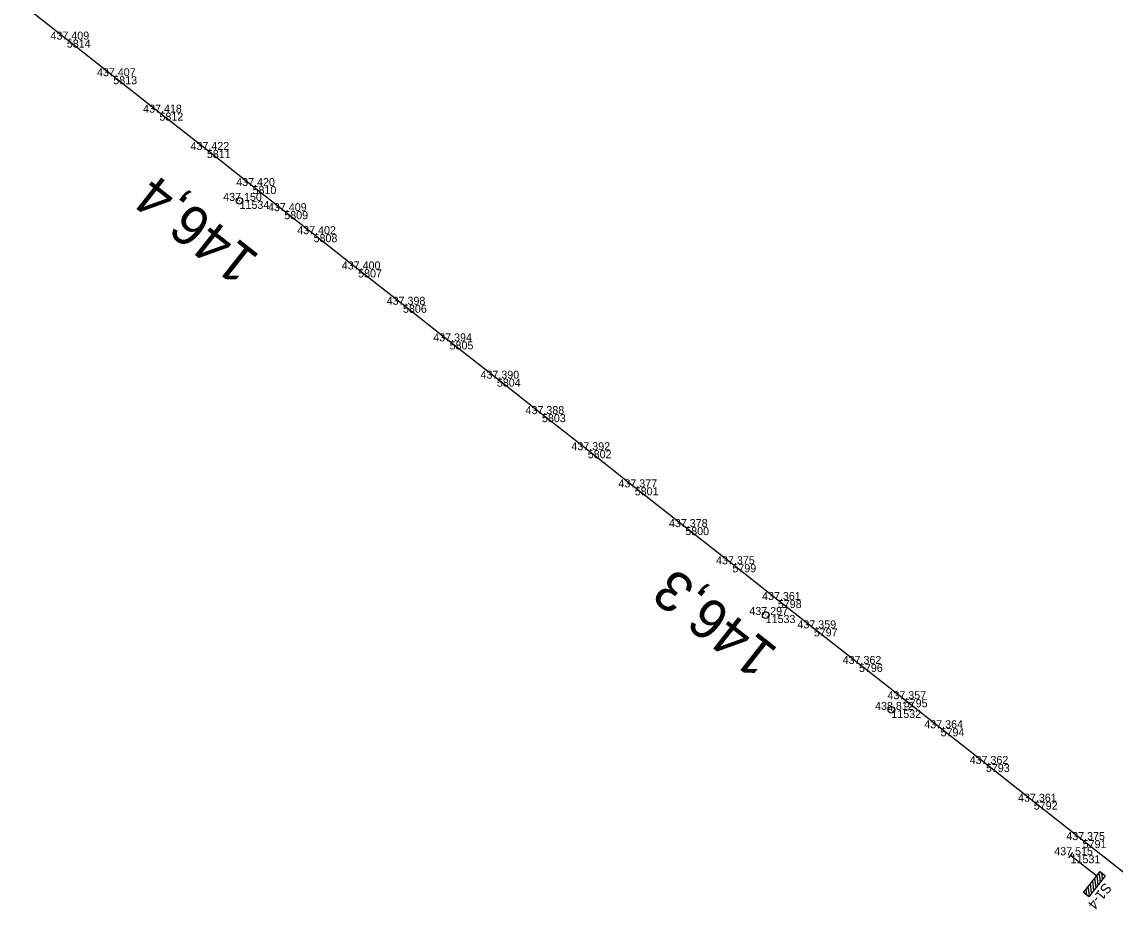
# Model space of a CAD drawing. Extents: x -654154 to -652650, y -1166925 to -1164904.
# Drawn here: x -653146.3 to -652982.4, y -1166045.8 to -1165912.8 of the extents above; entities that cross this region are included whole.
import ezdxf

# ---------------------------------------------------------------- set-up
doc = ezdxf.new("R2010")
doc.units = 0
for name, color, linetype in [('Vrstva 1', 7, 'Continuous'), ('Vrstva 50', 7, 'Continuous'), ('Vrstva 6', 7, 'Continuous'), ('Vrstva 60', 7, 'Continuous'), ('Vrstva 61', 7, 'Continuous'), ('Vrstva 7', 7, 'Continuous')]:
    doc.layers.add(name, color=color, linetype=linetype)

msp = doc.modelspace()

# ---------------------------------------------------------------- linework, layer by layer
at = {"layer": 'Vrstva 1'}
msp.add_lwpolyline([(-652979.33, -1166041.69), (-652987.25, -1166035.46), (-652994.58, -1166029.7), (-653001.76, -1166024.05), (-653008.55, -1166018.7), (-653014.07, -1166014.35), (-653020.79, -1166009.06), (-653027.56, -1166003.73), (-653032.96, -1165999.48), (-653039.77, -1165994.12), (-653046.84, -1165988.55), (-653054.41, -1165982.59), (-653061.46, -1165977.03), (-653068.33, -1165971.62), (-653075.09, -1165966.3), (-653082.18, -1165960.72), (-653089.16, -1165955.23), (-653095.89, -1165949.93), (-653102.57, -1165944.65), (-653106.96, -1165941.2), (-653111.72, -1165937.44), (-653118.57, -1165932.03), (-653125.68, -1165926.44), (-653132.6, -1165920.98), (-653139.57, -1165915.49), (-653146.31, -1165910.17)], dxfattribs=at)
at = {"layer": 'Vrstva 50'}
msp.add_line((-653015.98, -1166015.95), (-653015.88, -1166015.95), dxfattribs=at)
msp.add_circle((-653015.93, -1166015.95), 0.5, dxfattribs=at)
at = {"layer": 'Vrstva 6'}
for p, q in [((-652988.75, -1166037.33), (-652989.36, -1166038.12)), ((-652989.06, -1166037.73), (-652985.14, -1166040.81)), ((-652984.59, -1166041.72), (-652984.76, -1166040.32)), ((-652984.26, -1166041.3), (-652984.37, -1166040.4)), ((-652985.9, -1166043.39), (-652986.07, -1166041.98)), ((-652985.57, -1166042.97), (-652985.74, -1166041.57)), ((-652985.24, -1166042.55), (-652985.41, -1166041.15)), ((-652984.92, -1166042.14), (-652985.08, -1166040.73)), ((-652986.62, -1166043.72), (-652986.72, -1166042.81)), ((-652986.23, -1166043.8), (-652986.4, -1166042.4))]:
    msp.add_line(p, q, dxfattribs=at)
msp.add_lwpolyline([(-652984.65, -1166040.18), (-652983.86, -1166040.8), (-652986.34, -1166043.94), (-652987.12, -1166043.32)], close=True, dxfattribs=at)
at = {"layer": 'Vrstva 60'}
for p, q in [((-653139.57, -1165915.49), (-653139.57, -1165915.49)), ((-653132.6, -1165920.98), (-653132.6, -1165920.98)), ((-653125.68, -1165926.44), (-653125.68, -1165926.44)), ((-653118.57, -1165932.03), (-653118.57, -1165932.03)), ((-653111.72, -1165937.44), (-653111.72, -1165937.44)), ((-653113.67, -1165939.66), (-653113.67, -1165939.66)), ((-653106.96, -1165941.2), (-653106.96, -1165941.2)), ((-653102.57, -1165944.65), (-653102.57, -1165944.65)), ((-653095.89, -1165949.93), (-653095.89, -1165949.93)), ((-653089.16, -1165955.23), (-653089.16, -1165955.23)), ((-653082.18, -1165960.72), (-653082.18, -1165960.72)), ((-653075.09, -1165966.3), (-653075.09, -1165966.3)), ((-653068.33, -1165971.62), (-653068.33, -1165971.62)), ((-653061.46, -1165977.03), (-653061.46, -1165977.03)), ((-653054.41, -1165982.59), (-653054.41, -1165982.59)), ((-653046.84, -1165988.55), (-653046.84, -1165988.55)), ((-653039.77, -1165994.12), (-653039.77, -1165994.12)), ((-653032.96, -1165999.48), (-653032.96, -1165999.48)), ((-653034.78, -1166001.73), (-653034.78, -1166001.73)), ((-653027.56, -1166003.73), (-653027.56, -1166003.73)), ((-653020.79, -1166009.06), (-653020.79, -1166009.06)), ((-653014.07, -1166014.35), (-653014.07, -1166014.35)), ((-653015.93, -1166015.95), (-653015.93, -1166015.95)), ((-653008.55, -1166018.7), (-653008.55, -1166018.7)), ((-653001.76, -1166024.05), (-653001.76, -1166024.05)), ((-652994.58, -1166029.7), (-652994.58, -1166029.7)), ((-652987.25, -1166035.46), (-652987.25, -1166035.46)), ((-652989.06, -1166037.73), (-652989.06, -1166037.73))]:
    msp.add_line(p, q, dxfattribs=at)
at = {"layer": 'Vrstva 7'}
for p, q in [((-653113.63, -1165939.69), (-653113.71, -1165939.63)), ((-653034.74, -1166001.76), (-653034.82, -1166001.7))]:
    msp.add_line(p, q, dxfattribs=at)
for centre in [(-653113.67, -1165939.66), (-653034.78, -1166001.73)]:
    msp.add_circle(centre, 0.5, dxfattribs=at)

# ---------------------------------------------------------------- texts
at = {"layer": 'Vrstva 6'}
msp.add_text('S1-4', height=1.5, rotation=231.7942, dxfattribs=at).set_placement((-652983.95, -1166041.75))
at = {"layer": 'Vrstva 60'}
for s, p in [('5814', (-653139.57, -1165916.69)), ('5813', (-653132.6, -1165922.18)), ('5812', (-653125.68, -1165927.64)), ('5811', (-653118.57, -1165933.24)), ('5810', (-653111.72, -1165938.64)), ('11534', (-653113.67, -1165940.86)), ('5809', (-653106.96, -1165942.4)), ('5808', (-653102.57, -1165945.85)), ('5807', (-653095.89, -1165951.13)), ('5806', (-653089.16, -1165956.43)), ('5805', (-653082.18, -1165961.92)), ('5804', (-653075.09, -1165967.5)), ('5803', (-653068.33, -1165972.82)), ('5802', (-653061.46, -1165978.23)), ('5801', (-653054.41, -1165983.79)), ('5800', (-653046.84, -1165989.75)), ('5799', (-653039.77, -1165995.32)), ('5798', (-653032.96, -1166000.68)), ('11533', (-653034.78, -1166002.93)), ('5797', (-653027.56, -1166004.93)), ('5796', (-653020.79, -1166010.26)), ('5795', (-653014.07, -1166015.55)), ('11532', (-653015.93, -1166017.15)), ('5794', (-653008.55, -1166019.9)), ('5793', (-653001.76, -1166025.25)), ('5792', (-652994.58, -1166030.9)), ('5791', (-652987.25, -1166036.66)), ('11531', (-652989.06, -1166038.93))]:
    msp.add_text(s, height=1.2, dxfattribs=at).set_placement(p)
at = {"layer": 'Vrstva 61'}
for s, p in [('437.409', (-653142.02, -1165915.49)), ('437.407', (-653135.05, -1165920.98)), ('437.418', (-653128.13, -1165926.44)), ('437.422', (-653121.02, -1165932.03)), ('437.420', (-653114.17, -1165937.44)), ('437.150', (-653116.12, -1165939.66)), ('437.409', (-653109.41, -1165941.2)), ('437.402', (-653105.02, -1165944.65)), ('437.400', (-653098.34, -1165949.93)), ('437.398', (-653091.61, -1165955.23)), ('437.394', (-653084.63, -1165960.72)), ('437.390', (-653077.54, -1165966.3)), ('437.388', (-653070.79, -1165971.62)), ('437.392', (-653063.91, -1165977.03)), ('437.377', (-653056.86, -1165982.59)), ('437.378', (-653049.29, -1165988.55)), ('437.375', (-653042.22, -1165994.12)), ('437.361', (-653035.32, -1165999.48)), ('437.297', (-653037.23, -1166001.73)), ('437.359', (-653030.02, -1166003.73)), ('437.362', (-653023.24, -1166009.06)), ('437.357', (-653016.52, -1166014.35)), ('438.812', (-653018.38, -1166015.95)), ('437.364', (-653011, -1166018.7)), ('437.362', (-653004.2, -1166024.05)), ('437.361', (-652996.94, -1166029.7)), ('437.375', (-652989.71, -1166035.46)), ('437.515', (-652991.51, -1166037.73))]:
    msp.add_text(s, height=1.2, dxfattribs=at).set_placement(p)
at = {"layer": 'Vrstva 7'}
for s, rotation, p in [('146,4', 141.7473, (-653110.44, -1165947.96)), ('146,3', 141.7867, (-653032.72, -1166006.93))]:
    msp.add_text(s, height=6, rotation=rotation, dxfattribs=at).set_placement(p)

doc.saveas('drawing.dxf')
